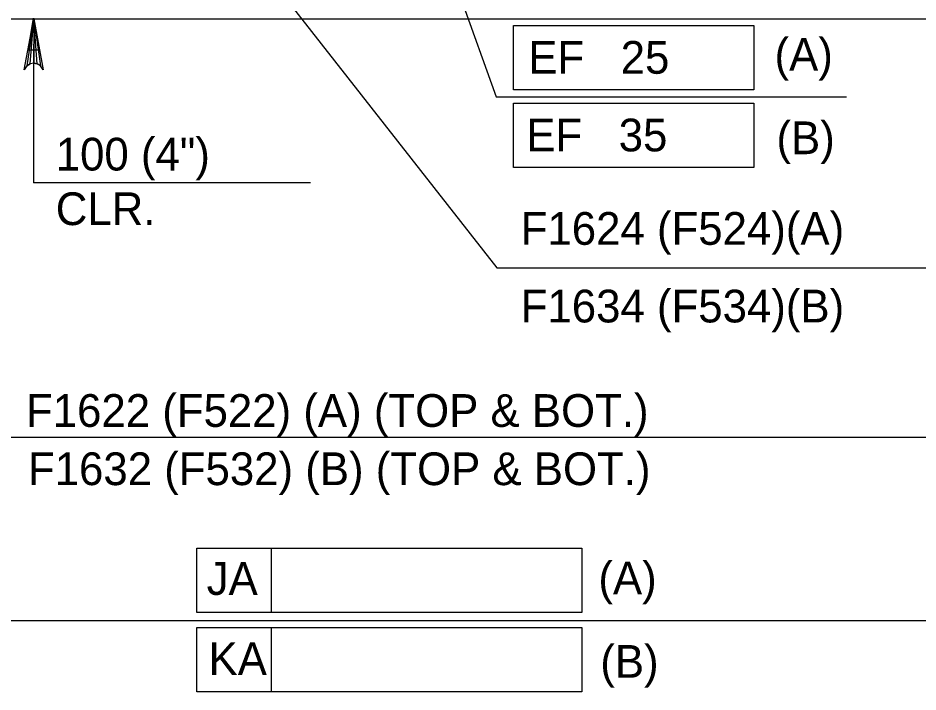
# Model space of a CAD drawing. Extents: x 634540 to 640306, y 296059 to 300275.
# Drawn here: x 639110.9 to 639193.4, y 296352.9 to 296414.7 of the extents above; entities that cross this region are included whole.
import ezdxf

# ---------------------------------------------------------------- set-up
doc = ezdxf.new("R2010")
doc.units = 0
for name, color, linetype in [('3', 7, 'Continuous'), ('4', 7, 'Continuous'), ('6', 7, 'Continuous'), ('9', 7, 'Continuous')]:
    doc.layers.add(name, color=color, linetype=linetype)

msp = doc.modelspace()

# ---------------------------------------------------------------- linework, layer by layer
at = {"layer": '4'}
for p, q in [((639125.246, 296429.518), (639154.822, 296391.783)), ((639150.116, 296420.422), (639154.776, 296407.459)), ((639156.349, 296413.989), (639178.39, 296413.989)), ((639156.349, 296408.082), (639156.349, 296413.989)), ((639178.39, 296413.989), (639178.39, 296408.082)), ((639112.37, 296412.266), (639112.37, 296399.571)), ((639178.39, 296408.082), (639156.349, 296408.082)), ((639154.776, 296407.459), (639186.888, 296407.459)), ((639156.349, 296406.876), (639178.39, 296406.876)), ((639156.349, 296400.969), (639156.349, 296406.876)), ((639178.39, 296406.876), (639178.39, 296400.969)), ((639178.39, 296400.969), (639156.349, 296400.969)), ((639154.822, 296391.783), (639199.489, 296391.783)), ((639095.488, 296376.278), (639201.635, 296376.278)), ((639127.34, 296366.105), (639162.641, 296366.105)), ((639127.34, 296360.199), (639127.34, 296366.105)), ((639134.184, 296360.199), (639134.184, 296366.105)), ((639162.641, 296366.105), (639162.641, 296360.199)), ((639162.641, 296360.199), (639127.34, 296360.199)), ((639091.421, 296359.476), (639205.699, 296359.476)), ((639127.34, 296358.819), (639162.641, 296358.819)), ((639127.34, 296352.913), (639127.34, 296358.819)), ((639134.184, 296352.913), (639134.184, 296358.819)), ((639162.641, 296358.819), (639162.641, 296352.913)), ((639162.641, 296352.913), (639127.34, 296352.913))]:
    msp.add_line(p, q, dxfattribs=at)
msp.add_lwpolyline([(639112.383, 296414.599), (639113.258, 296409.938), (639113.008, 296410.297), (639112.695, 296410.482), (639112.383, 296410.536), (639112.07, 296410.482), (639111.758, 296410.297), (639111.51, 296409.938), (639112.383, 296414.599), (639111.758, 296410.297), (639112.07, 296410.482), (639112.383, 296414.599), (639112.383, 296410.536), (639112.695, 296410.482), (639112.383, 296414.599), (639113.008, 296410.297)], dxfattribs=at)
msp.add_lwpolyline([(639112.862, 296411.724), (639111.878, 296411.724), (639112.37, 296414.676)], close=True, dxfattribs=at)
at = {"layer": '6'}
msp.add_line((639137.741, 296399.572), (639112.369, 296399.572), dxfattribs=at)
at = {"layer": '9'}
msp.add_line((639091.421, 296414.599), (639205.699, 296414.599), dxfattribs=at)

# ---------------------------------------------------------------- texts
at = {"layer": '3'}
for s, p in [('100 (4")', (639114.401, 296400.7)), ('CLR.', (639114.401, 296395.7))]:
    msp.add_text(s, height=3.0001, dxfattribs=at).set_placement(p)
at = {"layer": '4'}
for s, height, p in [('EF   25', 3.0001, (639157.718, 296409.57)), ('(A)', 3.0001, (639180.292, 296409.843)), ('EF   35', 3.0001, (639157.537, 296402.455)), ('(B)', 3.0001, (639180.469, 296402.198)), ('F1624 (F524)(A)', 3.00014, (639157.024, 296393.892)), ('F1634 (F534)(B)', 3.00014, (639157.024, 296386.779)), ('F1622 (F522) (A) (TOP & BOT.)', 3.00014, (639111.676, 296377.208)), ('F1632 (F532) (B) (TOP & BOT.)', 3.00014, (639111.853, 296371.87)), ('JA', 3.0001, (639128.238, 296361.813)), ('(A)', 3.0001, (639164.143, 296361.859)), ('KA', 3.0001, (639128.408, 296354.463)), ('(B)', 3.0001, (639164.32, 296354.215))]:
    msp.add_text(s, height=height, dxfattribs=at).set_placement(p)

doc.saveas('drawing.dxf')
